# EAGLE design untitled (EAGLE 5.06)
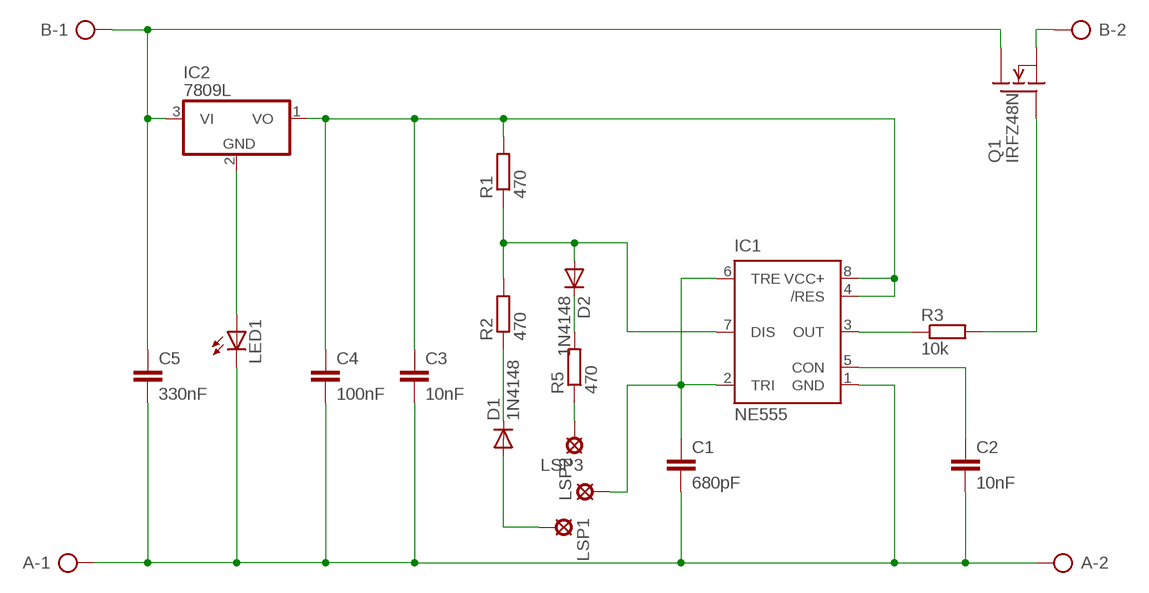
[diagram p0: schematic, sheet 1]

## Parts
A  AK300/2  [AK300/2]
B  AK300/2  [AK300/2]
C1  680pF  C5/2.5  [C5B2.5]
C2  10nF  C5/2.5  [C5B2.5]
C3  10nF  C5/2.5  [C5B2.5]
C4  100nF  C5/2.5  [C5B2.5]
C5  330nF  C5/2.5  [C5B2.5]
D1  1N4148  1N4148DO35-10  [DO35-10]
D2  1N4148  1N4148DO35-10  [DO35-10]
IC1  NE555  [DIL-08]
IC2  7809L  7808L  [TO92]
LED1  LED3MM  [LED3MM]
LSP1  MCS10B  [MCS10B]
LSP2  MCS10B  [MCS10B]
LSP3  MCS10B  [MCS10B]
Q1  IRFZ48N  IRF540  [TO220]
R1  470  R-EU_0207/10  [0207/10]
R2  470  R-EU_0207/10  [0207/10]
R3  10k  R-EU_0207/10  [0207/10]
R5  470  R-EU_0207/10  [0207/10]

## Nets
N$1: A.1 A.2 C1.2 C2.2 C3.2 C4.2 C5.2 IC1.1(GND) LED1.K(C)
N$2: D2.C R5.2
N$3: C2.1 IC1.5(CON)
N$5: IC1.3(OUT) R3.1
N$6: D2.A IC1.7(DIS) R1.1 R2.2
N$7: C1.1 IC1.2(TRI) IC1.6(TRE) LSP2.MP
N$8: D1.C R2.1
N$9: LSP3.MP R5.1
N$10: D1.A LSP1.MP
N$11: B.1 C5.1 IC2.3(VI) Q1.2(D)
N$12: B.2 Q1.3(S)
N$13: Q1.1(G) R3.2
N$14: C3.1 C4.1 IC1.4(/RES) IC1.8(VCC+) IC2.1(VO) R1.2
N$15: IC2.2(GND) LED1.A

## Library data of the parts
A B = con-ptr500:AK300/2: CONNECTOR
C1-C5 = capacitor-wima:C: CAPACITOR
D1 D2 = diode:1N4148: DIODE
IC1 = st-microelectronics:NE555: General purpose bipolar Timer
IC2 = linear:78*: Positive VOLTAGE REGULATOR Source: http://cache.national.com/ds/LM/LM78L05.pdf http://www.fairchildsemi.com/ds/LM/LM7805.pdf
LED1 = led:LED: LED
LSP1-LSP3 = solpad:MCS10B: SOLDER PAD
Q1 = transistor-fet:IRF540: N-Channel Enhancement MOSFET (HEXFET); 100V; 28A; 0,077Ohm
R1-R3 R5 = resistor:R-EU_: RESISTOR, European symbol

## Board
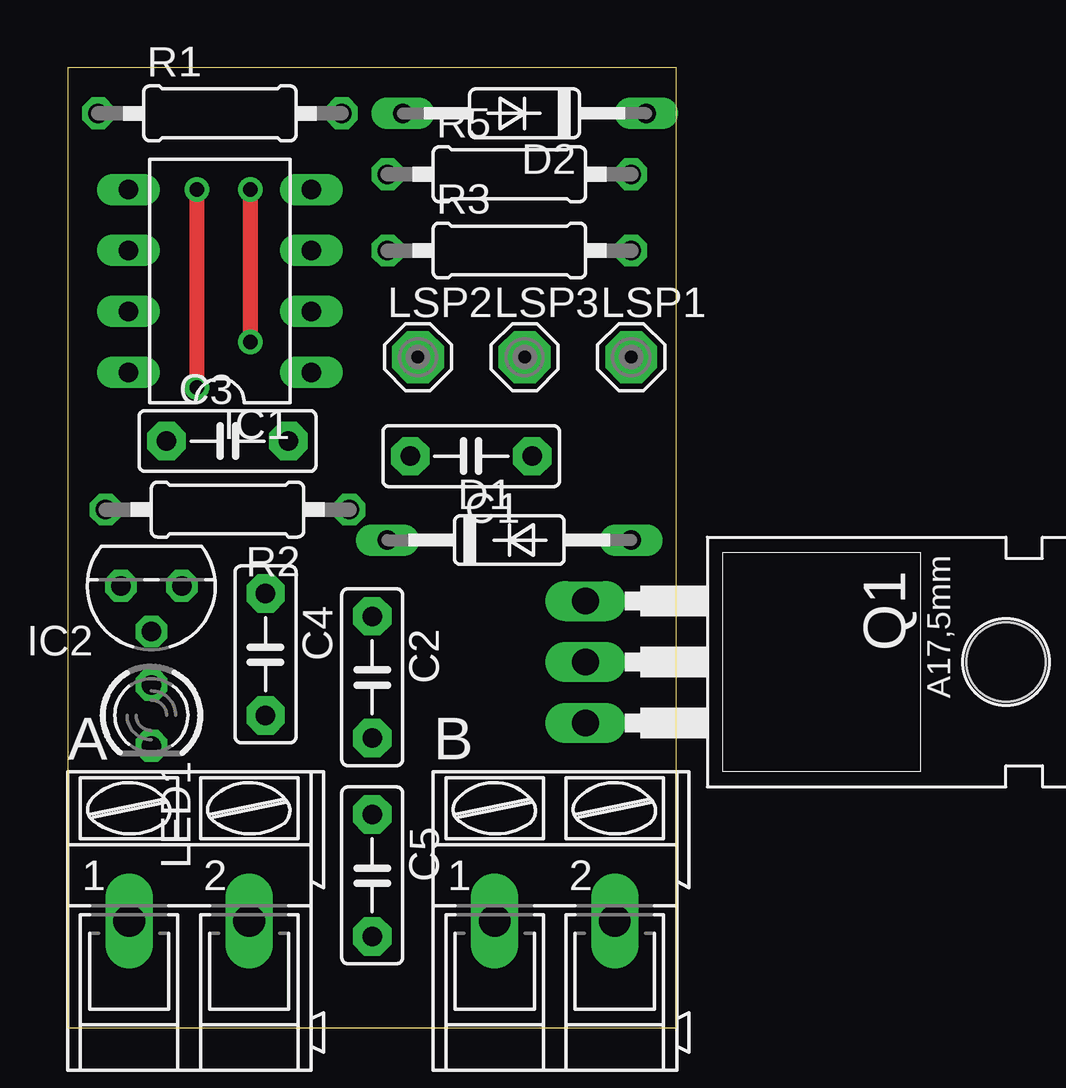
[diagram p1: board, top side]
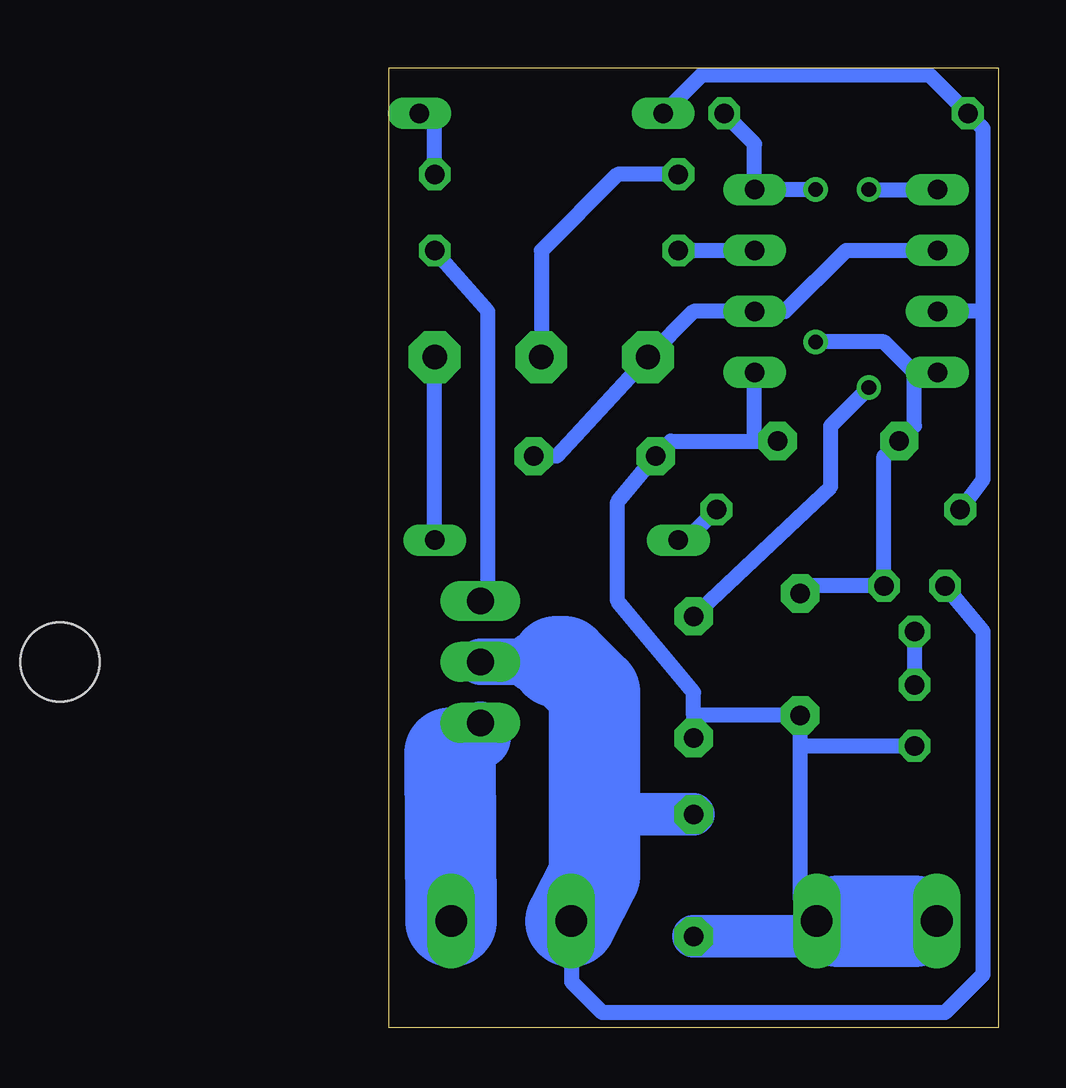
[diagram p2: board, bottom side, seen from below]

Size 25.39 x 39.99 mm. Coordinates in mm from the lower left corner, seen from the top.
Outline: 0,0 25.39,0 25.39,39.99 0,39.99 0,0
Copper layers (1*16): Top 0.035mm / dielectric 1.5mm / Bottom 0.035mm
Design rules "default *": minimum track width 25mil, minimum drill 24mil, track to track 8mil, track to pad 8mil, pad to pad 8mil, via to via 8mil, smd to smd 8mil, copper to edge 40mil, drill to drill 8mil, minimum pad ring 10mil, minimum via ring 8mil, stop-mask expansion 4mil, vias tented up to drill 0mil, thermal gap 10mil

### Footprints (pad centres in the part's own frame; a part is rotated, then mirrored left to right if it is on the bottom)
AK300/2 = drill 1.321 long: 1 -2.515,0; 2 2.489,0
C5B2.5 = drill 0.813 pad 1.6 octagon: 1 -2.54,0; 2 2.54,0
DO35-10 = drill 0.813 long: A 5.08,0; C -5.08,0
DIL-08 = drill 0.813 long: 1 -3.81,-3.81; 2 -1.27,-3.81; 3 1.27,-3.81; 4 3.81,-3.81; 5 3.81,3.81; 6 1.27,3.81; 7 -1.27,3.81; 8 -3.81,3.81
TO92 = drill 0.813 octagon: 1 -1.27,0; 2 0,1.905; 3 1.27,0
LED3MM = drill 0.813 octagon: A -1.27,0; K 1.27,0
MCS10B = drill 1.016 pad 2.159 octagon: MP 0,0
TO220 = drill 1.118 long: 1 -2.54,-6.35; 2 0,-6.35; 3 2.54,-6.35 | hole 3.302: 0,11.176
0207/10 = drill 0.813 octagon: 1 -5.08,0; 2 5.08,0

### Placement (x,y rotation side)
A  5.08,4.44 0 top
B  20.32,4.44 0 top
C1  16.83,23.81 180 top
C2  12.7,14.61 270 top
C3  6.67,24.45 0 top
C4  8.25,15.56 270 top
C5  12.7,6.35 270 top
D1  18.41,20.32 0 top
D2  19.05,38.1 180 top
IC1  6.35,31.12 90 top
IC2  3.49,18.41 180 top
LED1  3.49,13.02 270 top
LSP1  23.49,27.94 0 top
LSP2  14.61,27.94 0 top
LSP3  19.05,27.94 0 top
Q1  27.94,15.24 270 top
R1  6.35,38.1 0 top
R2  6.67,21.59 180 top
R3  18.41,32.38 0 top
R5  18.41,35.56 0 top

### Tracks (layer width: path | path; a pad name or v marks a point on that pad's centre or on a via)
N$1
  Bottom 0.635: 7.62,3.81 A.2 8.25,5.4 8.25,11.75 | 12.7,13.02 C2.2 | 12.7,13.02 12.7,13.97 15.88,17.78 15.88,21.91 C1.2 13.65,24.45 10.16,24.45 | 10.16,24.45 C3.2 | 10.16,24.45 IC1.1 | 12.7,13.02 C4.2 8.25,11.75 | 8.25,11.75 LED1.K
  Bottom 1.778: A.1 3.49,4.44 | 6.67,4.44 A.2 | 7.62,3.81 C5.2
  Bottom 3.81: 3.49,4.44 6.67,4.44
N$2
  Bottom 0.635: R5.2 23.49,38.1 D2.C
N$3  (via drill 0.61)
  Top 0.635: v5.4,26.67 v5.4,34.92
  Bottom 0.635: v5.4,34.92 IC1.5 | v5.4,26.67 6.98,25.08 6.98,22.54 C2.1
N$5
  Bottom 0.635: IC1.3 R3.1
N$6
  Bottom 0.635: 0.63,29.84 0.63,37.46 R1.1 2.86,39.69 12.38,39.69 D2.A | 0.63,29.84 IC1.7 | R2.2 0.63,22.86 0.63,29.84
N$7
  Bottom 0.254: 9.52,29.84 IC1.2
  Bottom 0.635: IC1.2 12.7,29.84 LSP2.MP 18.41,23.81 C1.1 | 9.52,29.84 8.89,29.84 6.35,32.38 3.17,32.38
  Bottom 0.762: IC1.6 3.17,32.38
N$8
  Bottom 0.635: D1.C 13.02,20.32 R2.1
N$9
  Bottom 0.635: LSP3.MP 19.05,32.38 15.88,35.56 R5.1
N$10
  Bottom 0.635: D1.A LSP1.MP
N$11
  Bottom 0.635: IC2.3 0.63,16.51 0.63,2.22 2.22,0.64 16.51,0.64 17.78,1.91 B.1
  Bottom 1.778: 16.83,8.89 C5.1
  Bottom 1.93: 19.37,15.24 Q1.2
  Bottom 2.54: 18.41,15.24 19.37,15.24
  Bottom 3.81: 18.41,15.24 18.1,15.24 16.83,13.97 16.83,8.89 16.83,6.35 B.1
N$12
  Bottom 1.778: 21.59,12.07 Q1.3
  Bottom 2.54: 22.86,11.43 21.59,12.07
  Bottom 3.81: B.2 22.86,11.43
N$13
  Bottom 0.635: R3.2 21.27,29.84 21.27,18.1 Q1.1
N$14  (via drill 0.61)
  Top 0.635: v7.62,28.57 v7.62,34.92
  Bottom 0.635: R1.2 10.16,36.83 IC1.4 v7.62,34.92 | C4.1 7.94,18.41 IC2.1 4.76,23.81 C3.1 3.49,25.08 3.49,27.3 | v7.62,28.57 4.76,28.57 3.49,27.3 | 3.49,27.3 IC1.8
N$15
  Bottom 0.635: IC2.2 LED1.A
